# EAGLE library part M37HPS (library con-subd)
SUB-D
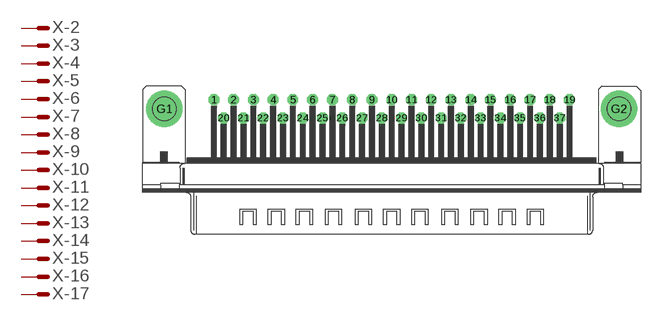
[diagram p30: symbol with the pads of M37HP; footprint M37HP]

Designator prefix X; gates -2=M -3=M -4=M -5=M -6=M -7=M -8=M -9=M -10=M -11=M -12=M -13=M -14=M -15=M -16=M -17=M -18=M -19=M -20=M -21=M -22=M -23=M -24=M -25=M -26=M -27=M -28=M -29=M -30=M -31=M -32=M -33=M -34=M -35=M -36=M -37=M -G=GND -1=MV

## M37HPS (OC_FARNELL: unknown; OC_NEWARK: unknown)  [M37HP]
1  -1:M  pas
2  -2:M  pas
3  -3:M  pas
4  -4:M  pas
5  -5:M  pas
6  -6:M  pas
7  -7:M  pas
8  -8:M  pas
9  -9:M  pas
10  -10:M  pas
11  -11:M  pas
12  -12:M  pas
13  -13:M  pas
14  -14:M  pas
15  -15:M  pas
16  -16:M  pas
17  -17:M  pas
18  -18:M  pas
19  -19:M  pas
20  -20:M  pas
21  -21:M  pas
22  -22:M  pas
23  -23:M  pas
24  -24:M  pas
25  -25:M  pas
26  -26:M  pas
27  -27:M  pas
28  -28:M  pas
29  -29:M  pas
30  -30:M  pas
31  -31:M  pas
32  -32:M  pas
33  -33:M  pas
34  -34:M  pas
35  -35:M  pas
36  -36:M  pas
37  -37:M  pas
G1  -G:G1  pas
G2  -G:G2  pas

## Footprint M37HP (pad centres in mm)
SUB-D
drill 1.016 octagon: 1 -24.841,1.27; 2 -22.098,1.27; 3 -19.329,1.27; 4 -16.561,1.27; 5 -13.818,1.27; 6 -11.049,1.27; 7 -8.28,1.27; 8 -5.512,1.27; 9 -2.769,1.27; 10 0,1.27; 11 2.769,1.27; 12 5.512,1.27; 13 8.28,1.27; 14 11.049,1.27; 15 13.792,1.27; 16 16.561,1.27; 17 19.329,1.27; 18 22.073,1.27; 19 24.841,1.27; 20 -23.47,-1.27; 21 -20.701,-1.27; 22 -17.958,-1.27; 23 -15.189,-1.27; 24 -12.421,-1.27; 25 -9.652,-1.27; 26 -6.909,-1.27; 27 -4.14,-1.27; 28 -1.372,-1.27; 29 1.372,-1.27; 30 4.14,-1.27; 31 6.909,-1.27; 32 9.652,-1.27; 33 12.421,-1.27; 34 15.189,-1.27; 35 17.932,-1.27; 36 20.701,-1.27; 37 23.47,-1.27
drill 3.302 pad 5.08 round: G1 -31.75,0; G2 31.75,0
